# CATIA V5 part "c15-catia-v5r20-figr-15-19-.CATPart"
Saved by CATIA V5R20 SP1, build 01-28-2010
Part number: Part1
Bounding box of the stored display mesh (mm): x -46.56 to 46.56, y -36.965 to 25.965, z 0 to 40
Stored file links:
  D:\v5_r20\psrt_files_downloaded\c15\c15-catia-v5r20-figr-15-19-.CATPart
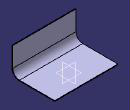
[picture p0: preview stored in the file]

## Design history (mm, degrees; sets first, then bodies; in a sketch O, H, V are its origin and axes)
SheetMetalParameters1: Thickness 1, BendRadius 1, KFactor 0.325257 {= log(min(100,max(20*SheetMetalParameters1.BendRadius,SheetMetalParameters1.Thickness)/SheetMetalParameters1.Thickness))/log(100)/2}, ReliefRadialLength 1, ReliefAxialLength 2, MinimumBendRadius 0
Body1 (main body)
  Sketch1 on xy-plane, origin (0, 0, 0), H (1, 0, 0), V (0, 1, 0)
    line L1 (-46.5596, 25.9646) -> (46.5596, 25.9646)
    line L2 (46.5596, 25.9646) -> (46.5596, -25.9646)
    line L3 (46.5596, -25.9646) -> (-46.5596, -25.9646)
    line L4 (-46.5596, -25.9646) -> (-46.5596, 25.9646)
    horizontal: L1 H, L3 H
    vertical: L2 V, L4 V
    symmetry: L1 L3 H, L4 L2 V
  Wall1: Thickness 1, Profile Sketch1
  d_NewWallOnEdge1: NewWallOnEdge_Edge edge [face of Wall1 | face of Wall1], NewWallOnEdge_Length 40, NewWallOnEdge_HeightLimitOffset 0, NewWallOnEdge_WidthOffset1 0, NewWallOnEdge_WidthOffset2 0, NewWallOnEdge_Angle 90, NewWallOnEdge_BendRadiusValue 10 {= d_NewWallOnEdge1.Clearance}, NewWallOnEdge_BendTable SheetMetalParameters1, KFacteur 0.5 {= log(min(100,max(20*d_NewWallOnEdge1.Radius,SheetMetalParameters1.Thickness)/SheetMetalParameters1.Thickness))/log(100)/2}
